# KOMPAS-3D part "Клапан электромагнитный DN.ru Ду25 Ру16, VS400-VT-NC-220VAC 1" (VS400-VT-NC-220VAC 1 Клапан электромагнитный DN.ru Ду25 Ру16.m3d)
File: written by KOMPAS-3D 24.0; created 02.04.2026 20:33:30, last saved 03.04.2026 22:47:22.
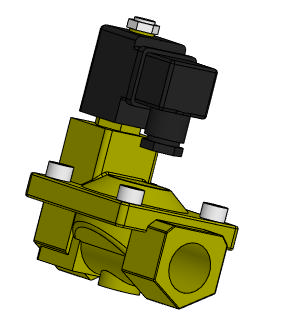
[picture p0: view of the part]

Document properties: Автор: artio; Полное имя файла: C:\Users\artio\OneDrive\Рабочий стол\Клапан электромагнитный DN.ru\VS400-VT-NC\VS400-VT-NC-220VAC 1 Клапан электромагнитный DN.ru Ду25 Ру16.m3d

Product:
- Body: Тело 1  | qty 1
    Масса: 1.76797
- Part/product: Клапан электромагнитный DN.ru Ду25 Ру16  | designation VS400-VT-NC-220VAC 1
    Масса: 1.524
    Раздел спецификации: Прочие изделия
    Примечание: D130-04700
    additional columns: ef56311e-7521-43dc-8291-0e6108b3d81d; VS400-ET-NC-220VAC 1; artio; c; Шероховатость не задана; Да

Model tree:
1. Операция без истории:1

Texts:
  VS400-VT-NC-220VAC 1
